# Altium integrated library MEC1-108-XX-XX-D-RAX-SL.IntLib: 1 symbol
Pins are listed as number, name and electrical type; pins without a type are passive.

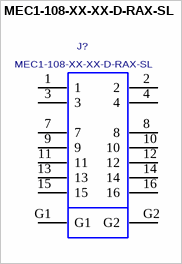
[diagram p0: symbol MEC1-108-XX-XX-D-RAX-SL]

## MEC1-108-XX-XX-D-RAX-SL
designator J?
1MM MEC1-RA ASSEMBLY.; MANUFACTURER: SAMTEC
footprint MEC1-108-XX-XX-D-RAX-SL
pins: 1, 2, 3, 4, 7, 8, 9, 10, 11, 12, 13, 14, 15, 16, G1, G2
